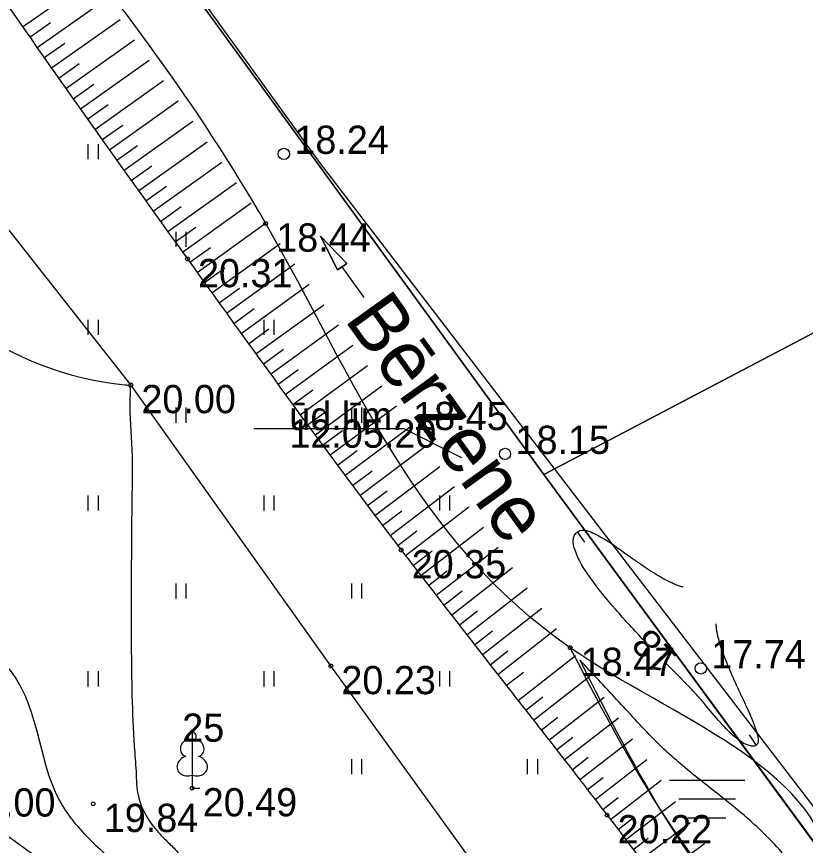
# Model space of a CAD drawing. Extents: x 521824 to 524158, y 294774 to 296228.
# Drawn here: x 522316.14 to 522347.56, y 295995.67 to 296028.68 of the extents above; entities that cross this region are included whole.
import ezdxf

# ---------------------------------------------------------------- set-up
doc = ezdxf.new("R2010")
doc.units = 0
for name, color, linetype in [('HIDG_AATZ_####_TKST_#', 7, 'Continuous'), ('HIDG_ELEM_####_####_#', 7, 'Continuous'), ('HIDG_HNOS_####_TKST_#', 7, 'Continuous'), ('HIDG_HORZ_####_TKST_#', 7, 'Continuous'), ('HIDG_HORZ_RESN_####_#', 7, 'Continuous'), ('HIDG_PLIN_####_####_#', 7, 'Continuous'), ('HIDG_UATZ_####_TKST_#', 7, 'Continuous'), ('RAMI_UZMR_####_####_#', 7, 'Continuous'), ('RELJ_AATZ_####_TKST_#', 7, 'Continuous'), ('RELJ_ELEM_####_####_#', 7, 'Continuous'), ('RELJ_HORZ_PAMT_####_#', 7, 'Continuous'), ('RELJ_HORZ_RESN_####_#', 7, 'Continuous'), ('RELJ_NOGA_####_####_#', 7, 'Continuous'), ('RELJ_NOGL_####_####_#', 7, 'Continuous'), ('ROBZ_IERR_####_####_#', 7, 'Continuous'), ('TERT_DIAM_####_TKST_#', 7, 'Continuous'), ('TERT_ELEM_####_####_#', 7, 'Continuous'), ('TERT_KOKR_####_####_#', 7, 'Continuous'), ('TERT_KONT_####_####_#', 7, 'Continuous')]:
    doc.layers.add(name, color=color, linetype=linetype)

msp = doc.modelspace()

# ---------------------------------------------------------------- linework, layer by layer
at = {"layer": 'HIDG_ELEM_####_####_#'}
for p, q in [((522328.243, 296019.935), (522329.295, 296018.843)), ((522328.929, 296018.583), (522328.243, 296019.935)), ((522329.295, 296018.843), (522328.929, 296018.583)), ((522329.982, 296017.491), (522329.112, 296018.713))]:
    msp.add_line(p, q, dxfattribs=at)
msp.add_lwpolyline([(522329.112, 296018.713), (522329.295, 296018.843), (522328.243, 296019.935), (522328.929, 296018.583), (522329.112, 296018.713)], dxfattribs=at)
for centre in [(522326.788, 296023.207), (522335.598, 296011.256), (522343.398, 296002.717)]:
    msp.add_circle(centre, 0.225, dxfattribs=at)
at = {"layer": 'HIDG_HORZ_RESN_####_#'}
for p, q in [((522338.775, 296007.748), (522338.482, 296008.153)), ((522345.322, 296000.067), (522345.599, 295999.65))]:
    msp.add_line(p, q, dxfattribs=at)
for points in [[(522341.139, 296003.822), (522340.569, 296004.432), (522339.998, 296005.071), (522338.99, 296006.336), (522338.386, 296007.422), (522338.319, 296007.835), (522338.359, 296007.999), (522338.399, 296008.069), (522338.425, 296008.1), (522338.439, 296008.116), (522338.454, 296008.13), (522338.584, 296008.202), (522339.155, 296008.087), (522340.223, 296007.419), (522341.464, 296006.564), (522342.089, 296006.204), (522342.392, 296006.064), (522342.539, 296006.008), (522342.684, 296005.961)], [(522343.991, 296004.487), (522344.007, 296004.325), (522344.035, 296004.153), (522344.124, 296003.787), (522344.404, 296002.99), (522345.138, 296001.355), (522345.65, 296000.07), (522345.653, 295999.712), (522345.562, 295999.631), (522345.489, 295999.619), (522345.445, 295999.62), (522345.422, 295999.622), (522345.41, 295999.624), (522345.397, 295999.626), (522345.113, 295999.73), (522344.815, 295999.934), (522344.189, 296000.55), (522343.551, 296001.294), (522343.237, 296001.658), (522342.931, 296001.986), (522341.993, 296002.94), (522341.991, 296002.942)]]:
    msp.add_spline(points, degree=3, dxfattribs=at)
at = {"layer": 'HIDG_PLIN_####_####_#'}
msp.add_spline([(522371.644, 295960.784), (522368.316, 295964.419), (522361.623, 295972.484), (522354.568, 295982.304), (522351.14, 295981.353), (522353.628, 295983.369), (522349.258, 295989.963), (522348.612, 295994.653), (522338.197, 296003.541), (522326.066, 296020.438), (522316.898, 296033.274), (522306.811, 296047.683), (522300.907, 296055.765), (522298.65, 296054.773), (522297.679, 296054.56), (522296.95, 296056.439), (522297.579, 296057.714), (522297.352, 296058.697), (522297.043, 296059.475), (522296.096, 296061.4), (522294.24, 296064.18)], degree=3, dxfattribs=at)
at = {"layer": 'HIDG_UATZ_####_TKST_#'}
msp.add_lwpolyline([(522325.597, 296012.265), (522331.563, 296012.265), (522333.864, 296011.11)], dxfattribs=at)
at = {"layer": 'RAMI_UZMR_####_####_#'}
msp.add_lwpolyline([(522238.336, 296053.36), (522285.718, 296059.481), (522293.257, 296061.848), (522296.155, 296062.191), (522300.201, 296058.476), (522312.508, 296044.556), (522328.24, 296022.822), (522349.854, 295994.636), (522373.592, 295961.698), (522362.138, 295957.162), (522349.174, 295950.882), (522342.278, 295948.544), (522332.736, 295938.071), (522327.686, 295933.811), (522322.022, 295927.668), (522307.813, 295919.973), (522290.212, 295909.174), (522273.707, 295894.679), (522210.195, 295852.819)], dxfattribs=at)
at = {"layer": 'RELJ_ELEM_####_####_#'}
for centre in [(522326.066, 296020.438), (522322.949, 296019.021), (522320.696, 296014.005), (522331.463, 296007.43), (522338.197, 296003.541), (522328.662, 296002.814), (522323.138, 295997.949), (522319.196, 295997.325), (522339.665, 295996.873)]:
    msp.add_circle(centre, 0.075, dxfattribs=at)
at = {"layer": 'RELJ_HORZ_PAMT_####_#'}
for points in [[(522307.511, 295998.353), (522310.22, 295996.893), (522312.21, 295995.364), (522313.381, 295991.433), (522311.202, 295989.415), (522310.175, 295988.62), (522309.966, 295987.416), (522313.85, 295985.088), (522316.525, 295983.236), (522317.705, 295982.514), (522320.626, 295981.982), (522321.772, 295982.859), (522321.645, 295987.826), (522322.285, 295989.319), (522322.784, 295990.627), (522321.927, 295992.647), (522320.526, 295994.503), (522319.11, 295995.854), (522317.84, 295997.472), (522315.7, 296002.839), (522308.755, 296003.516), (522307.511, 295998.353)], [(522350.444, 295987.239), (522350.102, 295987.875), (522349.906, 295988.28), (522348.589, 295990.204), (522348.328, 295990.849), (522348.165, 295991.525), (522348.025, 295992.207), (522347.832, 295992.871), (522347.433, 295994.016), (522346.864, 295995.087), (522346.267, 295995.78), (522345.624, 295996.416), (522344.25, 295997.577), (522342.849, 295998.695), (522341.526, 295999.894), (522340.787, 296000.677), (522340.056, 296001.467), (522338.587, 296003.041)], [(522313.472, 295997.942), (522313.488, 295997.934), (522313.5, 295997.924), (522315.325, 295991.761), (522314.926, 295990.374), (522315.004, 295986.438), (522317.314, 295984.446), (522317.494, 295984.338), (522317.935, 295984.258), (522318.108, 295984.39), (522318.313, 295985.311), (522318.786, 295986.541), (522320.007, 295991.384), (522319.417, 295993.04), (522318.975, 295993.539), (522313.564, 295997.934), (522313.521, 295997.969), (522313.48, 295997.973), (522313.472, 295997.942)]]:
    msp.add_spline(points, degree=3, dxfattribs=at)
at = {"layer": 'RELJ_HORZ_RESN_####_#'}
for points in [[(522312.89, 296017.237), (522314.224, 296016.319), (522320.464, 296014.012), (522320.618, 296013.964), (522320.652, 296013.907), (522320.667, 296013.681), (522320.725, 296011.673), (522320.737, 296009.664), (522320.708, 296005.644), (522320.739, 296001.624), (522320.828, 295999.616), (522320.899, 295998.612), (522320.992, 295997.609), (522321.797, 295996.179), (522321.984, 295995.979), (522322.179, 295995.789), (522322.372, 295995.6), (522322.556, 295995.401), (522324.079, 295993.532), (522324.746, 295992.528), (522325.039, 295991.992), (522325.3, 295991.426), (522325.457, 295990.537), (522325.464, 295989.365), (522325.438, 295988.193), (522325.415, 295987.021), (522325.433, 295985.85), (522325.499, 295984.7), (522325.62, 295983.55), (522325.695, 295982.4), (522325.683, 295981.825), (522325.659, 295981.538), (522325.621, 295981.251), (522325.324, 295980.639), (522324.747, 295980.184), (522324.111, 295979.902)], [(522322.913, 295979.655), (522321.949, 295979.608), (522320.54, 295979.731), (522319.851, 295979.891), (522319.179, 295980.096), (522317.917, 295980.69), (522315.759, 295982.063), (522315.446, 295982.267), (522313.62, 295983.254), (522311.693, 295984.076), (522309.783, 295984.906), (522308.873, 295985.378), (522308.011, 295985.917), (522307.807, 295986.14), (522307.699, 295986.435), (522307.73, 295987.149), (522307.851, 295987.506), (522308.003, 295987.849), (522308.45, 295988.437), (522308.98, 295988.861), (522309.525, 295989.263), (522310.072, 295989.666), (522310.607, 295990.089), (522311.224, 295990.609), (522311.515, 295990.883), (522311.784, 295991.163), (522311.079, 295993.121), (522310.063, 295993.856), (522309.041, 295994.55), (522308.006, 295995.213), (522306.951, 295995.853), (522304.459, 295997.273), (522301.991, 295998.733), (522301.401, 295999.154), (522300.867, 295999.604), (522300.016, 296000.175), (522299.144, 296000.709), (522297.347, 296001.681), (522295.519, 296002.591), (522293.689, 296003.492), (522291.82, 296004.28), (522289.895, 296004.935), (522287.974, 296005.64), (522287.034, 296006.067), (522286.572, 296006.31), (522286.117, 296006.575), (522285.571, 296007.153), (522285.37, 296007.504), (522285.179, 296007.854), (522284.955, 296008.435), (522284.855, 296009.097), (522284.807, 296010.509), (522284.605, 296011.779), (522284.311, 296012.264), (522284.091, 296012.452), (522283.815, 296012.597), (522282.958, 296012.808), (522282.098, 296012.828), (522280.808, 296012.723), (522280.379, 296012.702), (522279.819, 296012.657), (522279.259, 296012.561), (522278.139, 296012.321), (522277.02, 296012.194), (522276.462, 296012.238), (522276.183, 296012.299), (522275.904, 296012.39), (522275.35, 296012.976), (522275.08, 296013.802), (522274.776, 296014.934)]]:
    msp.add_spline(points, degree=3, dxfattribs=at)
at = {"layer": 'RELJ_NOGA_####_####_#'}
for p, q in [((522316.384, 296028.269), (522319.11, 296030.174)), ((522316.957, 296027.45), (522319.688, 296029.363)), ((522317.532, 296026.632), (522320.266, 296028.555)), ((522316.67, 296027.859), (522317.488, 296028.433)), ((522317.244, 296027.041), (522318.064, 296027.616)), ((522318.107, 296025.814), (522320.843, 296027.746)), ((522318.684, 296024.997), (522321.422, 296026.936)), ((522317.819, 296026.223), (522318.64, 296026.801)), ((522318.396, 296025.406), (522319.217, 296025.986)), ((522319.263, 296024.181), (522322.001, 296026.126)), ((522319.842, 296023.366), (522322.581, 296025.314)), ((522318.973, 296024.589), (522319.795, 296025.171)), ((522319.552, 296023.774), (522320.374, 296024.357)), ((522320.422, 296022.552), (522323.16, 296024.504)), ((522320.132, 296022.959), (522320.953, 296023.544)), ((522321.003, 296021.738), (522323.74, 296023.693)), ((522320.712, 296022.144), (522321.534, 296022.73)), ((522321.584, 296020.924), (522324.32, 296022.882)), ((522321.293, 296021.331), (522322.114, 296021.917)), ((522322.167, 296020.111), (522324.9, 296022.07)), ((522322.75, 296019.299), (522325.48, 296021.258)), ((522321.875, 296020.518), (522322.695, 296021.105)), ((522322.458, 296019.705), (522323.277, 296020.293)), ((522323.333, 296018.487), (522326.06, 296020.447)), ((522323.917, 296017.675), (522326.641, 296019.633)), ((522323.041, 296018.893), (522323.86, 296019.481)), ((522323.625, 296018.081), (522324.443, 296018.668)), ((522324.501, 296016.863), (522327.22, 296018.823)), ((522325.086, 296016.052), (522327.801, 296018.012)), ((522324.209, 296017.269), (522325.025, 296017.857)), ((522324.793, 296016.457), (522325.609, 296017.045)), ((522325.672, 296015.241), (522328.382, 296017.201)), ((522326.259, 296014.432), (522328.96, 296016.394)), ((522325.379, 296015.647), (522326.192, 296016.235)), ((522325.965, 296014.837), (522326.777, 296015.425)), ((522326.847, 296013.623), (522329.539, 296015.586)), ((522327.437, 296012.816), (522330.118, 296014.779)), ((522326.553, 296014.028), (522327.362, 296014.616)), ((522328.029, 296012.01), (522330.697, 296013.973)), ((522327.142, 296013.22), (522327.948, 296013.808)), ((522327.733, 296012.413), (522328.536, 296013.002)), ((522328.623, 296011.205), (522331.273, 296013.17)), ((522329.219, 296010.403), (522331.853, 296012.363)), ((522328.326, 296011.608), (522329.124, 296012.197)), ((522328.921, 296010.804), (522329.714, 296011.392)), ((522329.818, 296009.602), (522332.429, 296011.561)), ((522330.419, 296008.803), (522333.006, 296010.758)), ((522329.518, 296010.002), (522330.305, 296010.589)), ((522330.118, 296009.202), (522330.898, 296009.789)), ((522331.024, 296008.006), (522333.584, 296009.954)), ((522331.631, 296007.211), (522334.161, 296009.153)), ((522330.721, 296008.404), (522331.493, 296008.99)), ((522331.327, 296007.608), (522332.09, 296008.192)), ((522332.24, 296006.418), (522334.742, 296008.344)), ((522331.935, 296006.815), (522332.69, 296007.394)), ((522332.851, 296005.627), (522335.322, 296007.538)), ((522333.463, 296004.836), (522335.902, 296006.731)), ((522332.545, 296006.022), (522333.291, 296006.598)), ((522333.157, 296005.231), (522333.894, 296005.802)), ((522334.077, 296004.047), (522336.484, 296005.922)), ((522334.693, 296003.258), (522337.066, 296005.113)), ((522333.77, 296004.441), (522334.497, 296005.006)), ((522334.385, 296003.652), (522335.102, 296004.212)), ((522335.309, 296002.471), (522337.648, 296004.304)), ((522335.001, 296002.864), (522335.707, 296003.418)), ((522336.116, 296001.441), (522338.408, 296003.233)), ((522335.648, 296002.038), (522336.328, 296002.57)), ((522335.499, 296002.228), (522335.5, 296002.229)), ((522336.732, 296000.653), (522338.976, 296002.405)), ((522335.807, 296001.835), (522335.808, 296001.835)), ((522336.424, 296001.047), (522337.104, 296001.579)), ((522337.346, 295999.864), (522339.544, 296001.576)), ((522337.039, 296000.259), (522337.705, 296000.778)), ((522337.96, 295999.075), (522340.112, 296000.747)), ((522337.653, 295999.47), (522338.306, 295999.977)), ((522338.573, 295998.285), (522340.681, 295999.917)), ((522338.267, 295998.68), (522338.906, 295999.176)), ((522339.185, 295997.494), (522341.248, 295999.088)), ((522338.879, 295997.889), (522339.505, 295998.374)), ((522339.796, 295996.703), (522341.817, 295998.259)), ((522339.491, 295997.098), (522340.103, 295997.571)), ((522340.404, 295995.908), (522342.393, 295997.418)), ((522340.101, 295996.306), (522340.702, 295996.765)), ((522341.005, 295995.109), (522342.97, 295996.576)), ((522340.705, 295995.509), (522341.298, 295995.955)), ((522341.602, 295994.307), (522343.539, 295995.746))]:
    msp.add_line(p, q, dxfattribs=at)
for points in [[(522298.77, 296052.501), (522299.007, 296052.355), (522299.75, 296051.442), (522300.47, 296050.463), (522301.915, 296048.481), (522304.731, 296044.924), (522307.497, 296041.323), (522309.494, 296038.481), (522311.425, 296035.593), (522313.343, 296032.696), (522315.3, 296029.826), (522322.949, 296019.021), (522331.463, 296007.43), (522335.499, 296002.228)], [(522335.499, 296002.228), (522339.665, 295996.873), (522341.137, 295994.932), (522342.589, 295992.978), (522344.044, 295991.023), (522345.52, 295989.083), (522346.873, 295987.624), (522348.414, 295986.256), (522349.845, 295984.914), (522350.426, 295984.232), (522350.667, 295983.885), (522350.868, 295983.532), (522350.873, 295982.729), (522350.319, 295981.854), (522350.173, 295981.697)]]:
    msp.add_spline(points, degree=3, dxfattribs=at)
at = {"layer": 'RELJ_NOGL_####_####_#'}
msp.add_spline([(522351.272, 295981.739), (522351.95, 295983.299), (522346.926, 295990.804), (522338.197, 296003.541)], degree=3, dxfattribs=at)
at = {"layer": 'ROBZ_IERR_####_####_#'}
for points in [[(522380.027, 296030.421), (522347.967, 296016.117), (522337.144, 296010.443), (522300.416, 296060.924), (522268.4, 296105.967)], [(521982.721, 296071.944), (522030.783, 296022.794), (522033.554, 296023.535), (522231.747, 296043.148), (522293.95, 296059.25), (522300.416, 296060.924), (522337.144, 296010.443), (522362.112, 295976.434), (522359.108, 295971.285), (522349.756, 295955.259), (522172.848, 295833.392), (522168.097, 295830.304), (522159.466, 295824.695), (522157.572, 295823.464), (522100.03, 295786.069), (522037.633, 295748.407), (521945.66, 295684.513), (521914.938, 295661.444)], [(522380.027, 295949.512), (522362.112, 295976.434), (522337.144, 296010.443), (522347.967, 296016.117), (522380.027, 296030.421)]]:
    msp.add_lwpolyline(points, dxfattribs=at)
at = {"layer": 'TERT_ELEM_####_####_#'}
for p, q in [((522319, 296023), (522319, 296023.6)), ((522319.4, 296023), (522319.4, 296023.6)), ((522322.5, 296019.5), (522322.5, 296020.1)), ((522322.9, 296019.5), (522322.9, 296020.1)), ((522319, 296016), (522319, 296016.6)), ((522319.4, 296016), (522319.4, 296016.6)), ((522326, 296016), (522326, 296016.6)), ((522326.4, 296016), (522326.4, 296016.6)), ((522322.5, 296012.5), (522322.5, 296013.1)), ((522322.9, 296012.5), (522322.9, 296013.1)), ((522329.5, 296012.5), (522329.5, 296013.1)), ((522329.9, 296012.5), (522329.9, 296013.1)), ((522319, 296009), (522319, 296009.6)), ((522319.4, 296009), (522319.4, 296009.6)), ((522326, 296009), (522326, 296009.6)), ((522326.4, 296009), (522326.4, 296009.6)), ((522333, 296009), (522333, 296009.6)), ((522333.4, 296009), (522333.4, 296009.6)), ((522322.5, 296005.5), (522322.5, 296006.1)), ((522322.9, 296005.5), (522322.9, 296006.1)), ((522329.5, 296005.5), (522329.5, 296006.1)), ((522329.9, 296005.5), (522329.9, 296006.1)), ((522319, 296002), (522319, 296002.6)), ((522319.4, 296002), (522319.4, 296002.6)), ((522326, 296002), (522326, 296002.6)), ((522326.4, 296002), (522326.4, 296002.6)), ((522333, 296002), (522333, 296002.6)), ((522333.4, 296002), (522333.4, 296002.6)), ((522329.5, 295998.5), (522329.5, 295999.1)), ((522329.9, 295998.5), (522329.9, 295999.1)), ((522336.5, 295998.5), (522336.5, 295999.1)), ((522336.9, 295998.5), (522336.9, 295999.1)), ((522323.138, 295998.469), (522323.138, 295997.949)), ((522342.15, 295998.266), (522345.15, 295998.266)), ((522323.138, 295997.949), (522323.438, 295997.949)), ((522342.525, 295997.516), (522344.775, 295997.516)), ((522342.9, 295996.766), (522344.4, 295996.766))]:
    msp.add_line(p, q, dxfattribs=at)
for points in [[(522323.138, 296000.199), (522323.138, 295998.469)], [(522323.272, 295999.85), (522323.271, 295999.852)]]:
    msp.add_lwpolyline(points, dxfattribs=at)
for centre, major_axis, ratio, start_param, end_param in [((522323.139, 295999.974), (0, -0.225), 0.707107, 3.14537, 5.287485), ((522323.137, 295999.974), (0, -0.225), 0.707107, 0.995701, 3.137816), ((522322.946, 295999.532), (-0.058, -0.319), 0.861323, 3.141593, 6.283185), ((522323.33, 295999.532), (0.058, -0.319), 0.861323, 0, 3.141593), ((522323.004, 295998.838), (0.46, 0.143), 0.814445, 1.570796, 4.752015), ((522323.272, 295998.838), (-0.46, 0.143), 0.814445, 1.531171, 4.712389)]:
    msp.add_ellipse(centre, major_axis=major_axis, ratio=ratio, start_param=start_param, end_param=end_param, dxfattribs=at)
at = {"layer": 'TERT_KOKR_####_####_#'}
msp.add_lwpolyline([(522342.802, 295986.417), (522337.601, 295990.45), (522328.662, 296002.814), (522320.696, 296014.005), (522308.914, 296028.961), (522298.804, 296042.698)], dxfattribs=at)
at = {"layer": 'TERT_KONT_####_####_#'}
msp.add_spline([(522351.272, 295981.739), (522352.433, 295984.697), (522352.165, 295984.965), (522349.219, 295988.694), (522346.675, 295990.994), (522338.587, 296003.041)], degree=3, dxfattribs=at)

# ---------------------------------------------------------------- texts
at = {"layer": 'HIDG_AATZ_####_TKST_#'}
for s, p in [(' 18.24', (522326.788, 296023.207)), (' 18.15', (522335.598, 296011.256)), (' 17.74', (522343.398, 296002.717))]:
    msp.add_text(s, height=1.125, dxfattribs=at).set_placement(p)
at = {"layer": 'HIDG_HNOS_####_TKST_#'}
msp.add_text('Bērzene', height=2.25, rotation=305.6311, dxfattribs=at).set_placement((522329.169, 296016.618))
at = {"layer": 'HIDG_HORZ_####_TKST_#'}
msp.add_text('18', height=1.125, rotation=134.0999, dxfattribs=at).set_placement((522342.535, 296003.186))
at = {"layer": 'HIDG_UATZ_####_TKST_#'}
for s, p in [('ūd.līm. 18.45', (522327.007, 296012.207)), ('12.05.20', (522327.007, 296011.504))]:
    msp.add_text(s, height=1.125, dxfattribs=at).set_placement(p)
at = {"layer": 'RELJ_AATZ_####_TKST_#'}
for s, p in [(' 18.44', (522326.066, 296019.313)), (' 20.31', (522322.949, 296017.896)), (' 20.00', (522320.696, 296012.88)), (' 20.35', (522331.463, 296006.305)), (' 18.47', (522338.197, 296002.416)), (' 20.23', (522328.662, 296001.689)), (' 19.00', (522313.508, 295996.815)), (' 20.49', (522323.138, 295996.824)), (' 19.84', (522319.196, 295996.2)), (' 20.22', (522339.665, 295995.748))]:
    msp.add_text(s, height=1.125, dxfattribs=at).set_placement(p)
at = {"layer": 'TERT_DIAM_####_TKST_#'}
msp.add_text('25', height=1.125, dxfattribs=at).set_placement((522322.74, 295999.794))

doc.saveas('drawing.dxf')
